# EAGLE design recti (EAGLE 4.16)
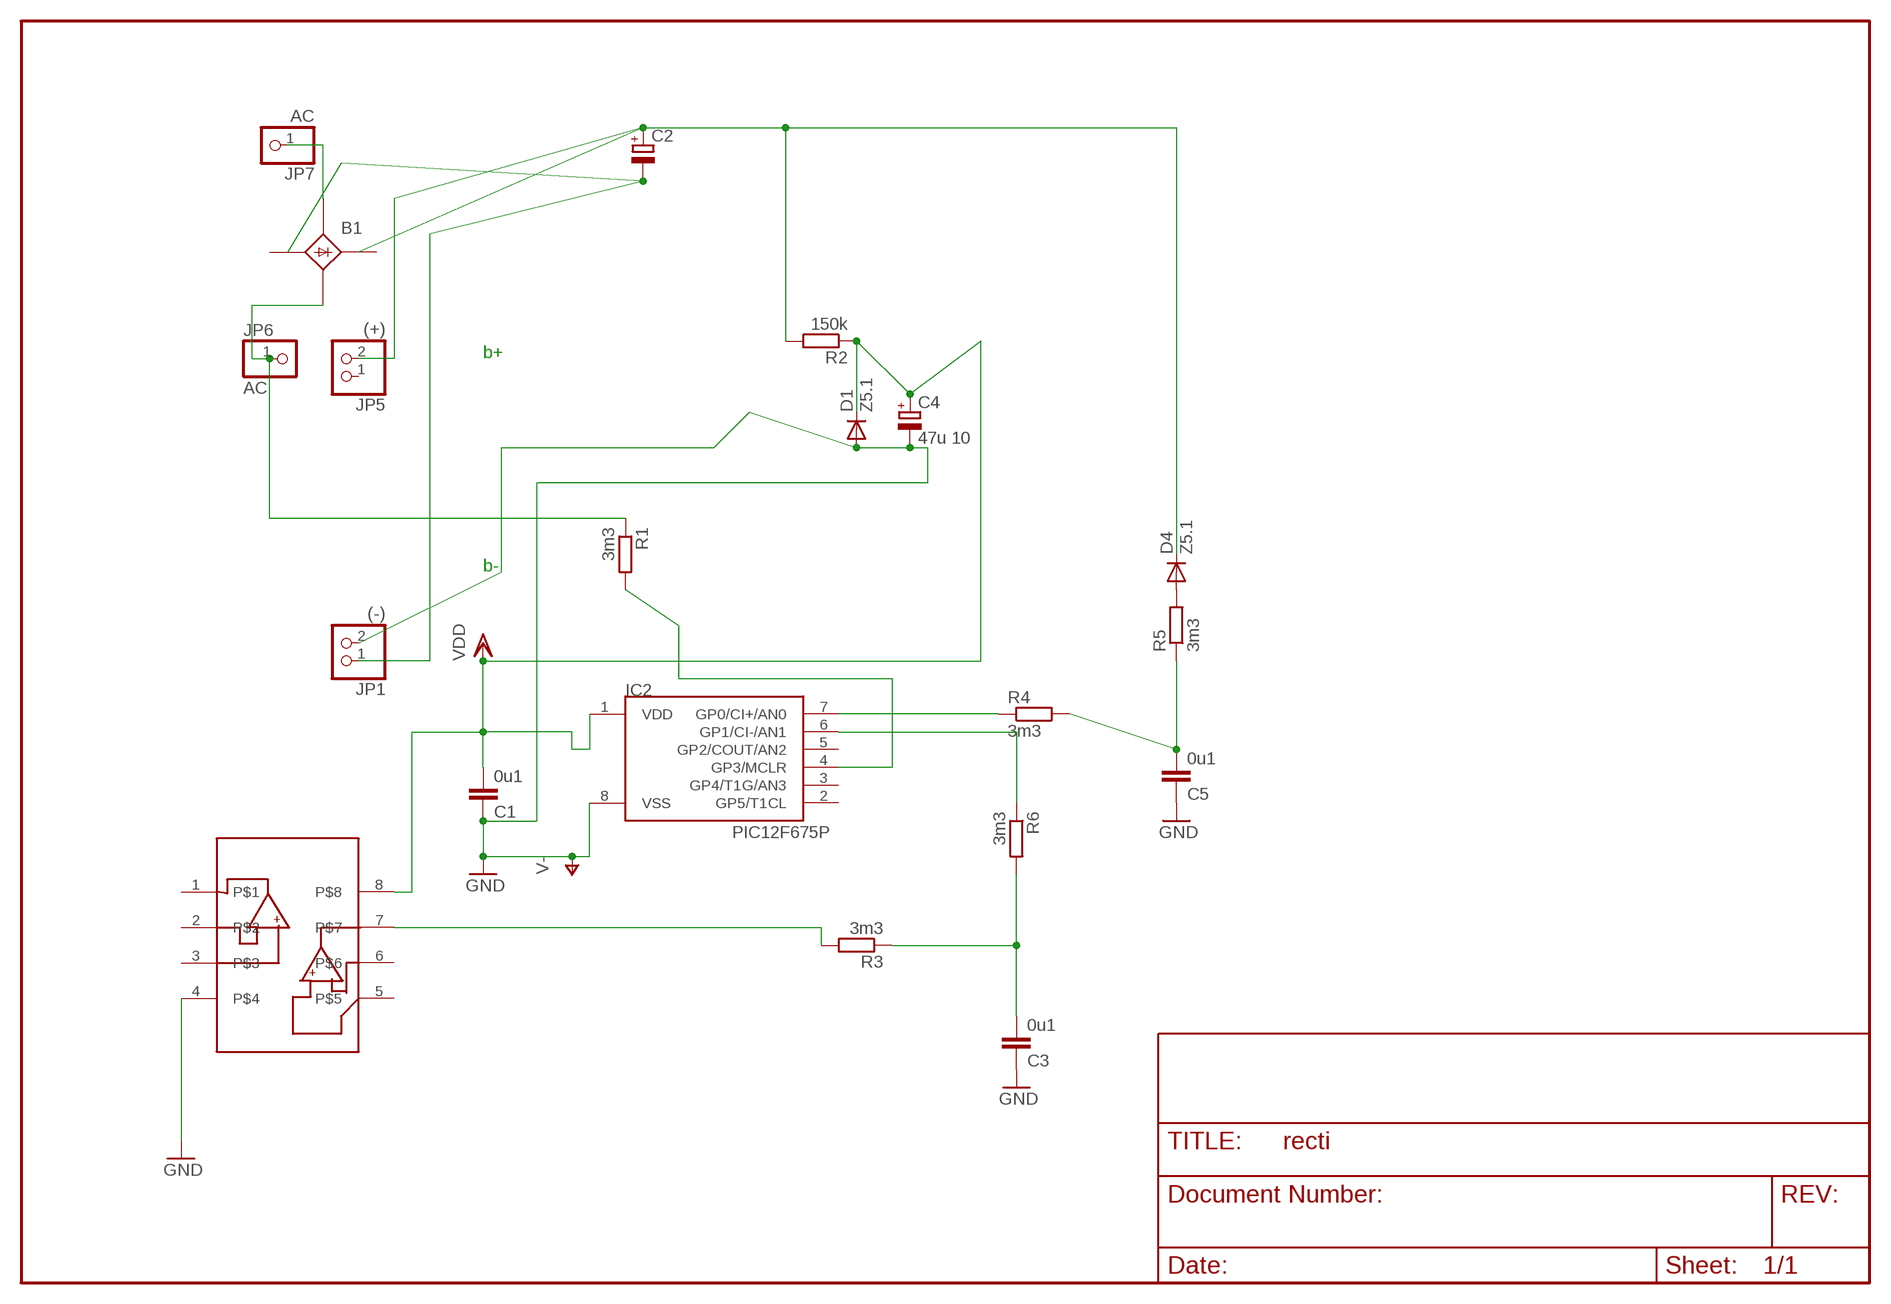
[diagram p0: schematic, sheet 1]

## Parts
B1  B25A-  [B25A-]
C1  0u1  C-EUC1206  [C1206]
C2  CPOL-EUE7.5-18  [E7,5-18]
C3  0u1  C-EUC1206  [C1206]
C4  47u 10  CPOL-EUSMCD  [SMC_D]
C5  0u1  C-EUC1206  [C1206]
D1  Z5.1  DIODE-MINIMELF  [MINIMELF]
D4  Z5.1  DIODE-MINIMELF  [MINIMELF]
IC2  PIC12F675P  [DIL8]
JP1  (-)  PINHD-1X2  [1X02]
JP5  (+)  PINHD-1X2  [1X02]
JP6  AC  PINHD-1X1  [1X01]
JP7  AC  PINHD-1X1  [1X01]
R1  3m3  R-EU_R1206  [R1206]
R2  150k  R-EU_R1206  [R1206]
R3  3m3  R-EU_R1206  [R1206]
R4  3m3  R-EU_R1206  [R1206]
R5  3m3  R-EU_R1206  [R1206]
R6  3m3  R-EU_R1206  [R1206]
U$1  MCP6042SOIC  [SO-08]

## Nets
GND: C3.1 C5.1 U$1.4
N$2: B1.AC1-(AC1) JP7.1
N$3: B1.AC2-(AC2) JP6.1 R1.1
N$5: C5.2 R4.2 R5.1
N$6: IC2.6(GP1/CI-/AN1) R6.1
N$7: D4.A R5.2
N$8: IC2.7(GP0/CI+/AN0) R4.1
N$9: C3.2 R3.1 R6.2
N$10: B1.+ C2.+ D4.C JP5.2 R2.2
N$11: R3.2 U$1.7
N$12: IC2.4(GP3/MCLR) R1.2
N$13: B1.- C2.- JP1.1
V-: C1.1 C4.- D1.A IC2.8(VSS) JP1.2 ; supply symbol labelled GND
VDD: C1.2 C4.+ D1.C IC2.1(VDD) R2.1 U$1.8
Unconnected: B1.+1(+) B1.-1(-) B1.AC1 B1.AC2 IC2.2(GP5/T1CL) IC2.3(GP4/T1G/AN3) IC2.5(GP2/COUT/AN2) JP5.1 U$1.1 U$1.2 U$1.3 U$1.5 U$1.6

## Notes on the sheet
- b+
- b-

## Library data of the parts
B1 = rectifier:B25A-: RECTIFIER 25-A bridge
C1 C3 C5 = rcl:C-EU: CAPACITOR, European symbol
C2 C4 = rcl:CPOL-EU: POLARIZED CAPACITOR, European symbol
D1 D4 = diode:DIODE-: DIODE
IC2 = microchip-3:PIC12F6*: uPC nW 1k Program Flash memory 2x Timer Comparator 10b A/D converter/ 4xIN
JP1 JP5 = pinhead:PINHD-1X2: PIN HEADER
JP6 JP7 = pinhead:PINHD-1X1: PIN HEADER
R1-R6 = rcl:R-EU_: RESISTOR, European symbol
U$1 = microchip-3:MCP6042

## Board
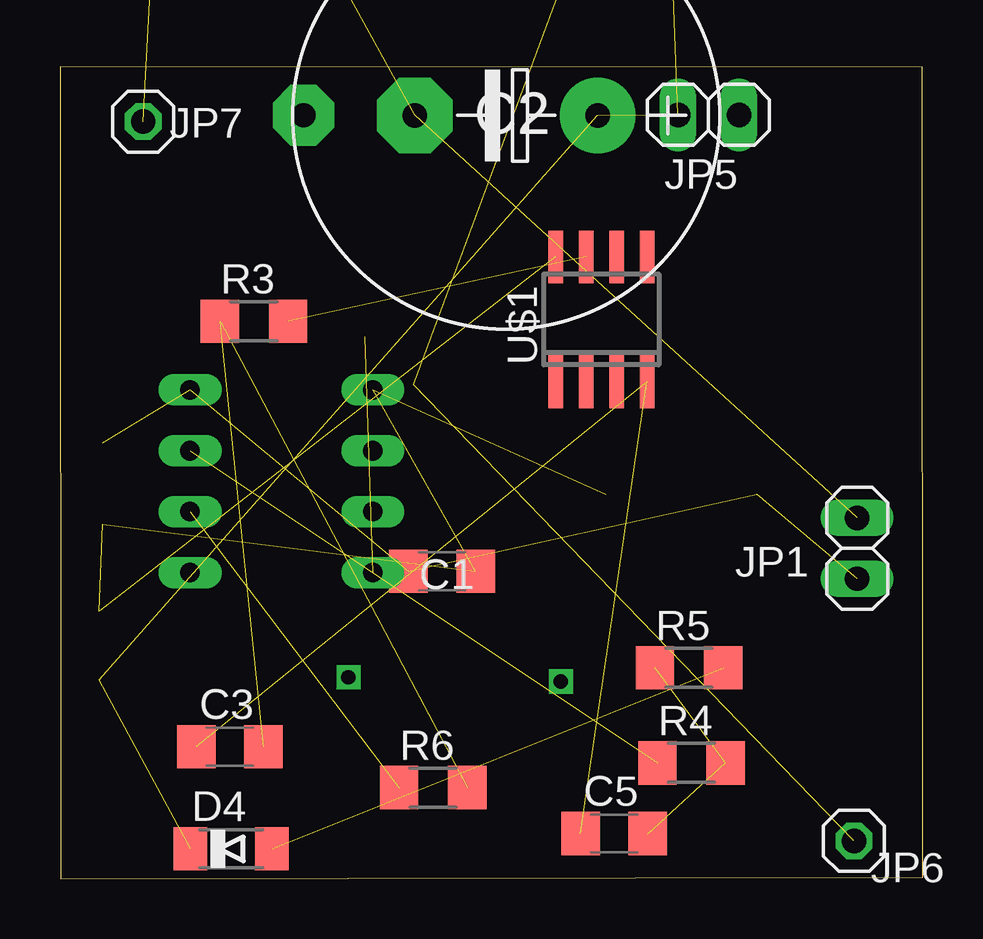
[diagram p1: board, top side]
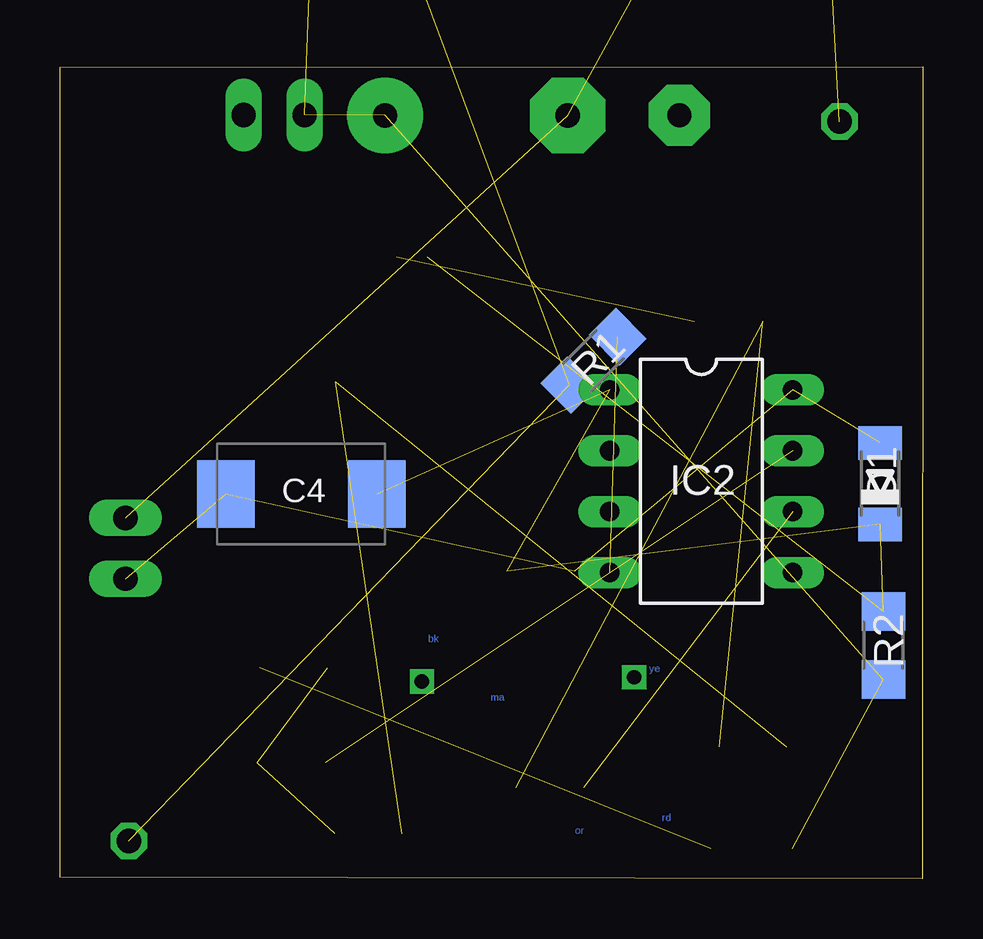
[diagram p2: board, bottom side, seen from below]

Size 35.97 x 33.82 mm. Coordinates in mm from the lower left corner, seen from the top.
Outline: 0.03,0 35.97,0.06 35.95,33.81 0,33.82 0.03,0
Copper layers (1*16): Top 0.035mm / dielectric 1.5mm / Bottom 0.035mm
Design rules "default": minimum track width 10mil, minimum drill 24mil, track to track 8mil, track to pad 8mil, pad to pad 8mil, via to via 8mil, smd to smd 8mil, copper to edge 40mil, drill to drill 8mil, minimum pad ring 10mil, minimum via ring 8mil, stop-mask expansion 4mil, vias tented up to drill 0mil, thermal gap 10mil

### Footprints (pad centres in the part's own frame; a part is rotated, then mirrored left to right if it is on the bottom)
B25A- = drill 2.007 pad 5.08 octagon: + -10.338,9.449; +1 -4.75,9.449; - 9.042,-4.343; -1 9.042,-9.931; AC1 9.042,4.343; AC1- 9.042,9.931; AC2 -9.042,-4.343; AC2- -9.042,-9.931 | hole 6.401: 0,0
C1206 = smd 1.6 x 1.8: 1 -1.4,0; 2 1.4,0
E7,5-18 = drill 1.016 pad 3.15 round: + -3.81,0 | drill 1.016 pad 3.15 octagon: - 3.81,0
SMC_D = smd 2.4 x 2.8: + -3.15,0; - 3.15,0
MINIMELF = smd 1.4 x 1.8: A 1.7,0; C -1.7,0
DIL8 = drill 0.813 long: 1 -3.81,-3.81; 2 -1.27,-3.81; 3 1.27,-3.81; 4 3.81,-3.81; 5 3.81,3.81; 6 1.27,3.81; 7 -1.27,3.81; 8 -3.81,3.81
1X02 = drill 1.016 long: 1 -1.27,0; 2 1.27,0
1X01 = drill 1.016 octagon: 1 0,0
R1206 = smd 1.6 x 1.803: 1 -1.422,0; 2 1.422,0
SO-08 = smd 0.6 x 2.2: 1 -1.905,-2.6; 2 -0.635,-2.6; 3 0.635,-2.6; 4 1.905,-2.6; 5 1.905,2.6; 6 0.635,2.6; 7 -0.635,2.6; 8 -1.905,2.6

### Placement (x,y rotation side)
B1  not placed on the board
C1  15.93,12.81 0 top
C2  18.61,31.8 180 top
C3  7.09,5.49 0 top
C4  25.91,16.02 180 bottom
C5  23.1,1.87 0 top
D1  1.78,16.45 90 bottom
D4  7.14,1.24 0 top
IC2  9.23,16.56 270 bottom
JP1  33.24,13.76 270 top
JP5  27.04,31.82 180 top
JP6  33.1,1.57 0 top
JP7  3.47,31.54 0 top
R1  13.73,21.57 44.9 bottom
R2  1.64,9.71 270 bottom
R3  8.09,23.22 0 top
R4  26.33,4.82 0 top
R5  26.23,8.78 0 top
R6  15.56,3.79 0 top
U$1  22.57,23.3 0 top

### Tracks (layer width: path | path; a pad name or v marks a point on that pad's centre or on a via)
GND  (2 unrouted)
N$2  (1 unrouted)
N$3  (2 unrouted)
N$5  (2 unrouted)
N$6  (1 unrouted)
N$7  (1 unrouted)
N$8  (1 unrouted)
N$9  (2 unrouted)
N$10  (4 unrouted)
N$11  (1 unrouted)
N$12  (1 unrouted)
N$13  (2 unrouted)
N$17  (via drill 0.6)
  other vias: 12.03,8.39
N$18  (via drill 1 pad 2.54)
  other vias: 10.15,31.81
N$19  (via drill 0.6)
  other vias: 20.88,8.21
V-  (4 unrouted)
VDD  (5 unrouted)

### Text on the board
Bottom: bk | ye | ma | rd | or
